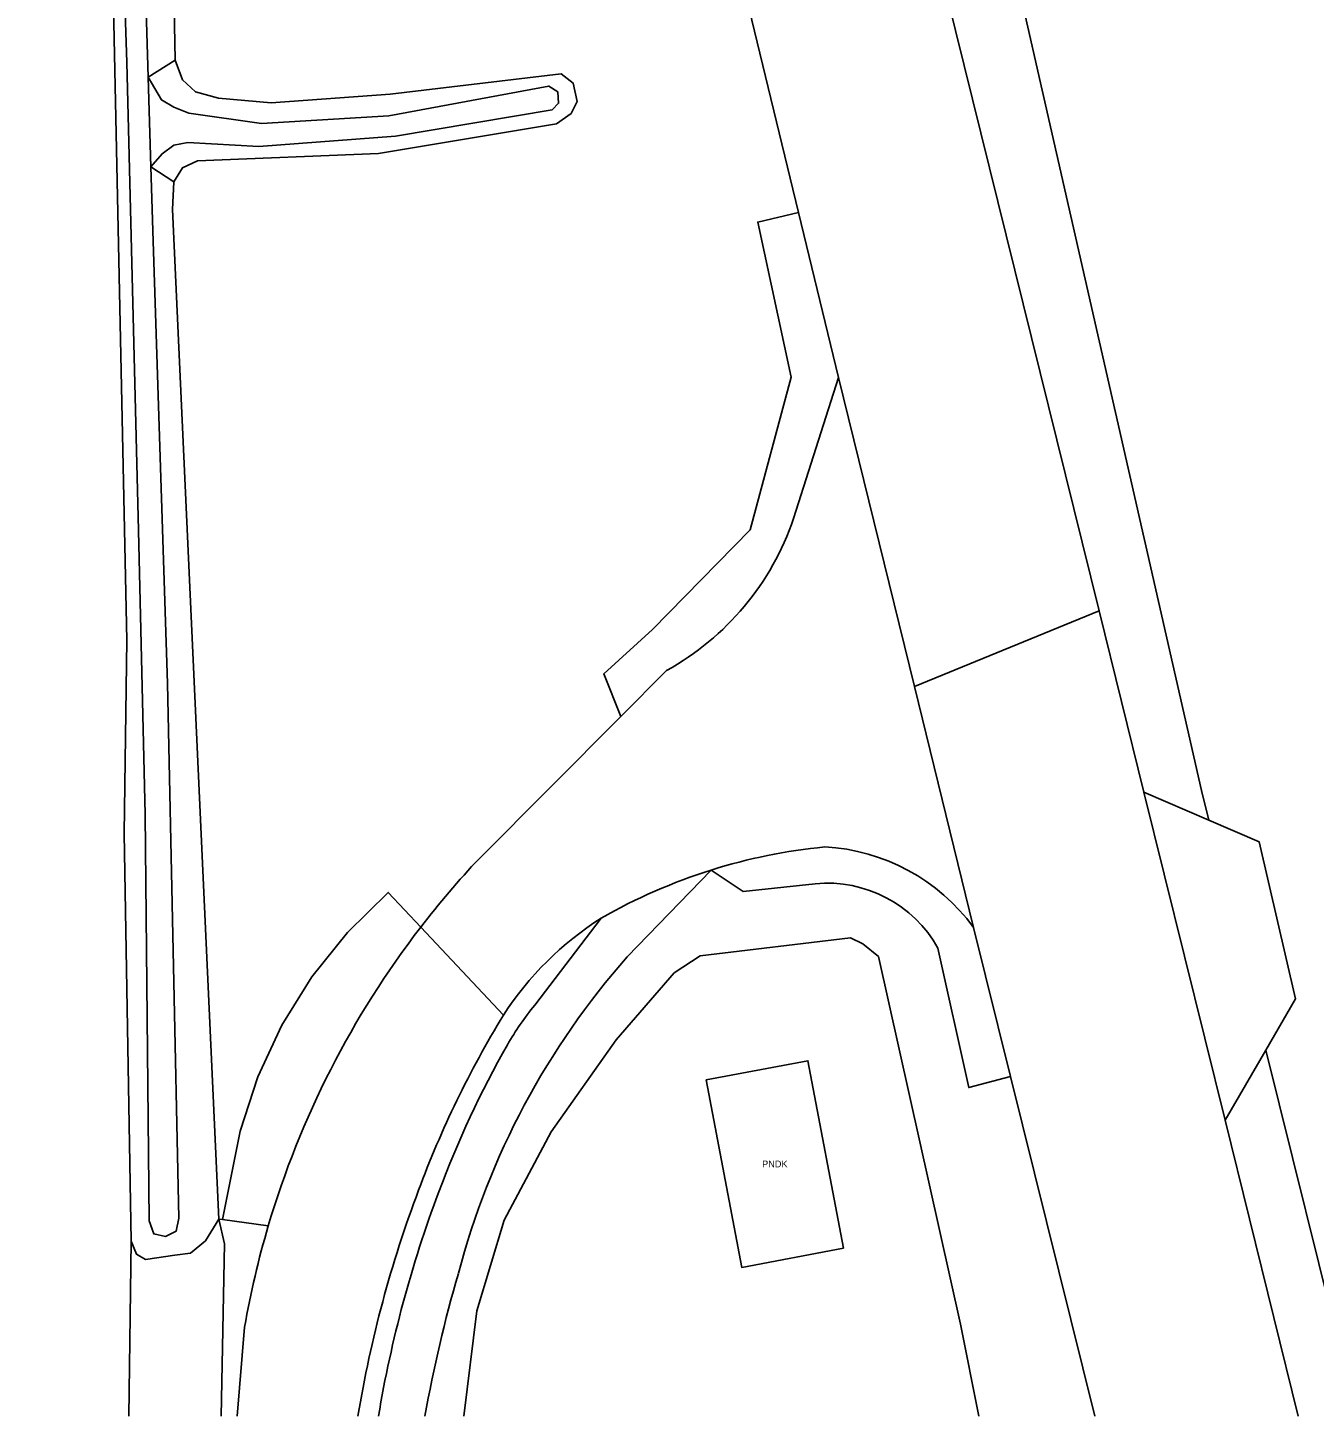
# Model space of a CAD drawing. Extents: x 134297 to 137000, y 403500 to 406000.
# Drawn here: x 135048.36 to 135085.95, y 403500 to 403540.57 of the extents above; entities that cross this region are included whole.
import ezdxf

# ---------------------------------------------------------------- set-up
doc = ezdxf.new("R2010")
doc.units = 0
doc.layers.add('gx-grn-maaiveld', color=7, linetype='Continuous')
doc.layers.add('kenmerkpunt-x pandkandidaat', color=7, linetype='Continuous')

msp = doc.modelspace()

# ---------------------------------------------------------------- linework, layer by layer
at = {"layer": 'gx-grn-maaiveld'}
for p, q in [((135062.261, 403570.76), (135070.881, 403535.18)), ((135079.665, 403523.534), (135075.051, 403542.196)), ((135052.671, 403539.629), (135051.882, 403539.135)), ((135051.882, 403539.135), (135051.96, 403536.513)), ((135052.632, 403536.074), (135051.96, 403536.513)), ((135070.881, 403535.18), (135072.051, 403530.351)), ((135072.051, 403530.351), (135070.74, 403526.23)), ((135072.051, 403530.351), (135074.269, 403521.325)), ((135074.269, 403521.325), (135079.665, 403523.534)), ((135080.975, 403518.235), (135079.665, 403523.534)), ((135067.029, 403521.791), (135065.691, 403520.449)), ((135075.999, 403514.285), (135074.269, 403521.325)), ((135065.691, 403520.449), (135061.558, 403516.302)), ((135080.975, 403518.235), (135083.345, 403508.652)), ((135082.867, 403517.419), (135080.975, 403518.235)), ((135068.328, 403515.96), (135065.88, 403513.426)), ((135063.174, 403512.011), (135065.117, 403514.553)), ((135062.26, 403511.72), (135059.845, 403514.292)), ((135076.347, 403512.871), (135075.999, 403514.285)), ((135077.077, 403509.929), (135076.347, 403512.871)), ((135083.345, 403508.652), (135084.534, 403510.7)), ((135084.534, 403510.7), (135087.189, 403500)), ((135077.077, 403509.929), (135079.541, 403500)), ((135083.345, 403508.652), (135085.484, 403500)), ((135054.049, 403505.746), (135053.95, 403505.76)), ((135054.049, 403505.746), (135055.391, 403505.56)), ((135051.319, 403500), (135051.382, 403505.111)), ((135054.484, 403500), (135054.698, 403502.604))]:
    msp.add_line(p, q, dxfattribs=at)
for points in [[(135051.547, 403636.977), (135051.729, 403605.035), (135052.037, 403572.947), (135052.671, 403539.629)], [(135048.364, 403630.258), (135049.411, 403602.803), (135050.564, 403555.535), (135051.255, 403522.678), (135051.179, 403517.029), (135051.382, 403505.111)], [(135050.103, 403600.862), (135050.41, 403587.22), (135050.487, 403573.462), (135050.948, 403557.284), (135050.986, 403547.715), (135051.255, 403539.568), (135051.601, 403525.887), (135051.793, 403517.586), (135051.909, 403505.712), (135052.043, 403505.328), (135052.389, 403505.251), (135052.697, 403505.404), (135052.773, 403505.789), (135052.447, 403521.41), (135052.024, 403534.341), (135051.96, 403536.513)], [(135051.882, 403539.135), (135051.563, 403549.867), (135051.371, 403561.28), (135051.063, 403574.423), (135050.948, 403589.141), (135050.91, 403600.247)], [(135082.867, 403517.419), (135082.653, 403518.282), (135077.159, 403542.442), (135076.463, 403543.981)], [(135052.671, 403539.629), (135052.882, 403539.052), (135053.267, 403538.706), (135053.939, 403538.514), (135055.476, 403538.38), (135058.954, 403538.629), (135063.95, 403539.225), (135064.296, 403538.956), (135064.411, 403538.418), (135064.238, 403538.072), (135063.815, 403537.765), (135058.608, 403536.9), (135053.324, 403536.689), (135052.882, 403536.477), (135052.632, 403536.074)], [(135051.882, 403539.135), (135052.267, 403538.466), (135052.632, 403538.255), (135053.074, 403538.082), (135055.188, 403537.774), (135058.916, 403538.005), (135063.585, 403538.87), (135063.854, 403538.697), (135063.873, 403538.37), (135063.681, 403538.178), (135059.108, 403537.409), (135055.111, 403537.102), (135053.036, 403537.217), (135052.632, 403537.14), (135052.287, 403536.891), (135051.96, 403536.513)], [(135052.632, 403536.074), (135052.594, 403535.267), (135053.95, 403505.76)], [(135070.881, 403535.18), (135069.692, 403534.894), (135070.664, 403530.364), (135069.466, 403525.898), (135066.616, 403522.986), (135065.192, 403521.692), (135065.691, 403520.449)], [(135084.534, 403510.7), (135085.401, 403512.194), (135084.346, 403516.781), (135082.867, 403517.419)], [(135068.328, 403515.96), (135069.261, 403515.338), (135071.372, 403515.562)], [(135059.845, 403514.292), (135058.894, 403515.307), (135057.707, 403514.139), (135056.667, 403512.838), (135055.789, 403511.423), (135055.086, 403509.914), (135054.567, 403508.332), (135054.049, 403505.746)], [(135061.101, 403500), (135061.485, 403503.081), (135062.283, 403505.729), (135063.651, 403508.306), (135065.552, 403511.003), (135067.249, 403512.957), (135068.007, 403513.458), (135072.399, 403513.975), (135072.762, 403513.808), (135073.222, 403513.432), (135075.611, 403502.686), (135076.149, 403500)], [(135077.077, 403509.929), (135075.858, 403509.604), (135074.955, 403513.676)], [(135072.194, 403504.914), (135071.158, 403510.39), (135068.186, 403509.827), (135069.222, 403504.351), (135072.194, 403504.914)], [(135053.95, 403505.76), (135053.554, 403505.129), (135053.119, 403504.764), (135052.664, 403504.705), (135051.805, 403504.582), (135051.537, 403504.732), (135051.382, 403505.111)], [(135054.014, 403500), (135054.109, 403505.039), (135053.95, 403505.76)]]:
    msp.add_lwpolyline(points, dxfattribs=at)
for centre, radius, start, end in [((135063.124, 403528.826), 8.046, 299.0315, 341.1773), ((135073.212, 403500.45), 16.261, 95.5034, 107.4808), ((135071.35, 403510.883), 5.761, 36.1947, 86.9824), ((135081.252, 403497.783), 27.034, 136.7613, 142.3608), ((135073.216, 403500.438), 16.273, 107.4786, 119.8457), ((135071.723, 403511.882), 3.697, 29.0328, 95.4448), ((135070.132, 403506.638), 9.37, 122.3608, 147.1558), ((135081.009, 403497.995), 26.712, 142.4022, 163.5475), ((135082.905, 403498.404), 22.705, 138.5765, 165.2721), ((135070.915, 403505.813), 9.917, 141.3145, 149.4243), ((135087.766, 403496.204), 29.855, 148.6861, 159.6086), ((135088.39, 403496.133), 29.891, 150.489, 159.5983), ((135092.363, 403494.321), 34.82, 159.3399, 170.6128), ((135092.99, 403494.259), 34.856, 159.3473, 170.5201), ((135081.305, 403497.926), 27.015, 163.5846, 170.0273), ((135099.707, 403492.886), 40.372, 163.7611, 169.8512)]:
    msp.add_arc(centre, radius, start, end, dxfattribs=at)

# ---------------------------------------------------------------- texts
at = {"layer": 'kenmerkpunt-x pandkandidaat'}
msp.add_text('PNDK', height=0.2, dxfattribs=at).set_placement((135069.819, 403507.271))

doc.saveas('drawing.dxf')
